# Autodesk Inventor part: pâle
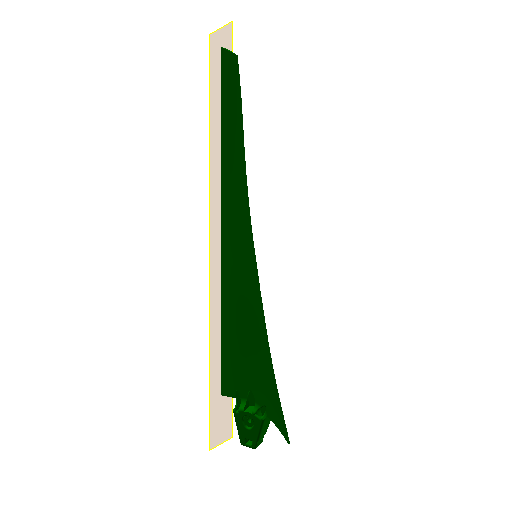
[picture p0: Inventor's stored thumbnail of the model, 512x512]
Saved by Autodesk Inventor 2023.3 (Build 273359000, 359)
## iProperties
Created: 2014-09
Part Number: pâle
Material: Générique
Document SubType Name: Modeling
Designer: papa
Density: 1 g/cm^3
Appearance: Par défaut
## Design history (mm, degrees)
node "pâle1"
node "pâle"
node "Base1"
